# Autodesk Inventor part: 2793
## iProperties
Author: Administrator
Shininess: 64.0
Angle Display Precision: 2
Document Length Units: 11272
Document Angle Units: 11286
Document Time Units: 11279
Document Mass Units: 11290
Document Length Units Precision: 3
Document Angle Units Precision: 2
Compacted: True
PropertySet Name: _Private Model Information
Created: 2002-03
Part Number: 2793
Material: Stainless Steel, 440C
Document SubType Name: Modeling
Designer: Administrator
Control State: 0
Master: False
Checked Out: False
PropertySet Name: Design Tracking Control
Density: 0.0
Volumn: 0.0
Area: 0.0
PropertySet Name: Model Information
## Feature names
1. Revolution1
